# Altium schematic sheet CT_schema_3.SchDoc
size 300 x 177 mm
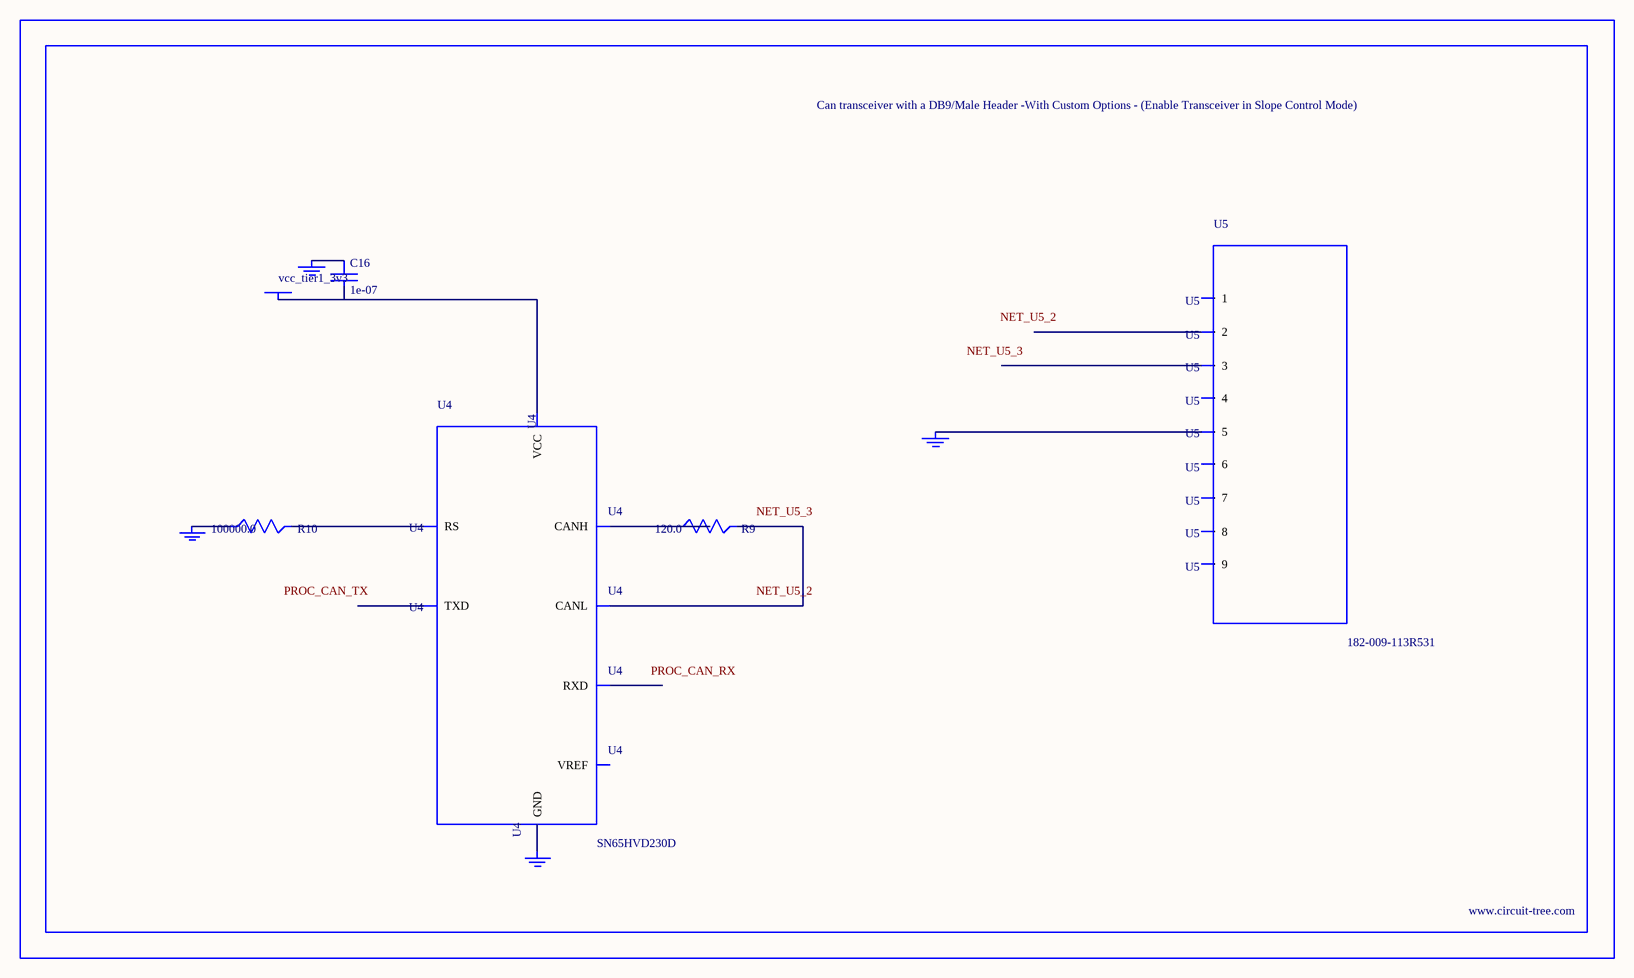
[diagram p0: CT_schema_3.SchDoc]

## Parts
BORDER2  (no value)
C16  1e-07  [C0402]
GND_INSTANCE_2_0  (no value)
GND_INSTANCE_2_1  (no value)
GND_INSTANCE_2_2  (no value)
GND_INSTANCE_2_3  (no value)
POWER_INSTANCE_2_0  vcc_tier1_3v3
R9  120.0  [R0603]
R10  100000.0  [R0603]
U4  SN65HVD230D  [SOIC-8]
U5  182-009-113R531  [182-009-MALE]

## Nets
NetC16_1: C16.1 GND_INSTANCE_2_0.0(GND)
NetC16_2: C16.2 POWER_INSTANCE_2_0.0(PWR) U4.3(VCC)
NetGND_INSTANCE_2_1_0: GND_INSTANCE_2_1.0(GND) R10.1
NetGND_INSTANCE_2_2_0: GND_INSTANCE_2_2.0(GND) U4.2(GND)
NetGND_INSTANCE_2_3_0: GND_INSTANCE_2_3.0(GND) U5.5
NetR9_1: R9.1 U4.7(CANH)
NetR9_2: R9.2 U4.6(CANL)
NetR10_2: R10.2 U4.8(RS)

Not connected (* = marked no-connect by the designer): U4 1(TXD) 4(RXD) 5(VREF); U5 1 2 3 4 6 7 8 9

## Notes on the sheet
- Labels drawn without touching a wire or pin: NET_U5_2, NET_U5_3, PROC_CAN_RX, PROC_CAN_TX

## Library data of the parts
BORDER2 = BORDER_PAGE2
C16 = C0402C104K3RACTU
GND_INSTANCE_2_0-GND_INSTANCE_2_3 = GND
POWER_INSTANCE_2_0 = PWR
R9 = RC0603JR-07120RL
R10 = RC0603JR-07100KL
